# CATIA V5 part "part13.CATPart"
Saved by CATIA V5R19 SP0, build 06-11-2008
Part number: part13
Bounding box of the stored display mesh (mm): x -5.243 to 4.306, y 0 to 10, z -0.01 to 15.28
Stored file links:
  U:\Busbar in SheetMetal\Busbar - Copy.CATPart
  Part3.CATPart
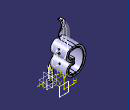
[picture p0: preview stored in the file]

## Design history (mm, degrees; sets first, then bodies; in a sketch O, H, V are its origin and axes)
SheetMetalParameters1: BendRadius 0.7, ReliefAxialLength 2, ReliefRadialLength 1, MinimumBendRadius 0, Thickness 0.8, KFactor 0.31076 {= log(min(100,max(20*SheetMetalParameters1.BendRadius,SheetMetalParameters1.Thickness)/SheetMetalParameters1.Thickness))/log(100)/2}
Set1
  Plane1: type Offset, Offset 1, RefPlane zx-plane
  Plane2: type Offset, Offset 4, RefPlane Plane1
  Plane3: type Offset, Offset 0.01, RefPlane Plane1
  Plane4: type Offset, Offset 0.1, RefPlane Plane2, reversed
  Sketch1 on zx-plane, origin (0, 0, 0), H (-1, 0, 0), V (0, 0, 1)
    arc A1 centre (-1.3046, 11.0693) radius 6 from (2.5521, 6.473) to (3.2916, 14.926) ccw
    arc A2 centre (5, 2) radius 5 from (1.7861, 5.8302) to (0, 2) ccw
    line L1 (0, 2) -> (0, 0)
    point P4 (0, 0)
    line L2 (1.7861, 5.8302) -> (2.5521, 6.473)
    construction line L3 (-1.3046, 11.0693) -> (2.5521, 6.473)
    construction line L4 (-1.3046, 11.0693) -> (3.2916, 14.926)
    point P7 (3.2916, 14.926)
    construction line L5 (5, 2) -> (1.7861, 5.8302)
    axis line L6 (5, 2) -> (0, 2)
    length L1 = 2
    radius A2 = 5
    angle L5 L6 = 50
    length L2 = 1
    radius A1 = 6
    angle L4 L3 = 90
    tangency: L1 A2, L2 A2, A1 L2
    horizontal: L6 H
    coincidence: P4 O
  Sketch2 on Plane3, origin (0, 1.01, 0), H (-1, 0, 0), V (0, 0, 1)
    arc A1 centre (-1.3046, 11.0693) radius 6 from (2.5521, 6.473) to (3.2916, 14.926) ccw
    point P2 (2.5521, 6.473)
    point P3 (3.2916, 14.926)
    reference projected point E1 (3.2916, 14.926) from Sketch1.P7
    reference projected point E2 (2.5521, 6.473) from vertex [element of Sketch1 | element of Sketch1]
    reference projected arc E3 centre (-1.3046, 11.0693) radius 6 from (2.5521, 6.473) to (3.2916, 14.926) ccw from Sketch1.A1
    coincidence: P3 E1, P2 E2, A1 E3
  Sketch3 on Plane2, origin (0, 5, 0), H (-1, 0, 0), V (0, 0, 1)
    construction line L1 (-1.3046, 14.5693) -> (-1.3046, 7.5693)
    construction line L2 (1.1954, 11.0693) -> (-3.8046, 11.0693)
    point P3 (1.1954, 11.0693)
    point P5 (-1.3046, 11.0693)
    ellipse A1 centre (-1.3046, 11.0693) semi-axes 3.5, 2.5 rotation 270 from (-1.3046, 7.5693) to (-1.3046, 14.5693)
    line L3 (-1.3046, 14.5693) -> (-2.3046, 14.5693)
    line L4 (-1.3046, 7.5693) -> (-2.3046, 7.5693)
    construction line L5 (-2.3046, 14.5693) -> (-2.3046, 7.5693)
    arc A2 centre (-2.3046, 13.1193) radius 1.45 from (-2.3046, 14.5693) to (-2.3046, 11.6693) ccw
    point P8 (-2.3046, 13.1193)
    point P9 (-2.3046, 11.6693)
    arc A3 centre (-2.3046, 9.0193) radius 1.45 from (-2.3046, 10.4693) to (-2.3046, 7.5693) ccw
    point P10 (-2.3046, 9.0193)
    point P11 (-2.3046, 10.4693)
    point P12 (-2.3046, 11.6693)
    line L6 (-2.3046, 11.6693) -> (-1.7046, 11.6693)
    line L7 (-2.3046, 10.4693) -> (-1.7046, 10.4693)
    point P14 (-2.3046, 10.4693)
    construction line L8 (-1.7046, 10.4693) -> (-1.7046, 11.6693)
    axis line L9 (-1.7046, 11.0693) -> (-3.8046, 11.0693)
    point P16 (-1.7046, 11.0693)
    construction circle A4 centre (-1.3046, 11.0693) radius 6
    reference projected arc E1 centre (-1.3046, 11.0693) radius 6 from (2.5521, 6.473) to (3.2916, 14.926) ccw from Sketch1.A1
    "Radius" A1 = 3.5
    distance A1 L1 = 2.5
    distance L5 L1 = 1
    distance L8 L5 = 0.6
    radius A2 = 1.45
    distance L6 L7 = 1.2
    vertical: L1 V, L5 V, L8 V
    horizontal: L2 H, L3 H, L4 H, L9 H
    midpoint: P5 L2, P5 L1, P16 L8
    coincidence: A1 P3, P8 L5, A2 P9, P9 L5, P10 L5, L5 P11, L5 P12, P14 A3, A4 E1
    tangency: A2 L3, A3 L4, L6 A2, L7 A3, A1 L4, A1 L3
  Sketch4 on Plane4, origin (0, 4.9, 0), H (-1, 0, 0), V (0, 0, 1)
    axis line L1 (-1.3046, 14.5693) -> (-1.3046, 7.5693)
    point P1 (-1.3046, 14.5693)
    point P2 (-1.3046, 7.5693)
    point P3 (-1.3046, 11.0693)
    ellipse A1 centre (-1.3046, 11.0693) semi-axes 3.5, 2.5 rotation 90 from (-1.3046, 7.5693) to (-1.3046, 14.5693)
    reference projected point E1 (-1.3046, 14.5693) from vertex [element of Sketch3 | element of Sketch3]
    reference projected point E2 (-1.3046, 7.5693) from vertex [element of Sketch3 | element of Sketch3]
    reference projected curve E3 from Sketch3.A1
    vertical: L1 V
    midpoint: P3 L1
    coincidence: P1 E1, P2 E2, A1 E3
  Extrude1: Lim1 3, Lim2 0, FirstUpto Plane1, Element1 Sketch1, Direction zx-plane
  Extrude2: Lim1 3, Lim2 0, FirstUpto Plane1, Element1 Sketch2, Direction Plane3
  Extrude3: Lim1 3, Lim2 0, FirstUpto Plane2, Element1 Sketch4, Direction Plane4
  Extrude4: Lim1 5, Lim2 0, Element1 Sketch3, Direction Plane2
  Loft1: Sections (Sketch2; Sketch4), EndSectionTangent Plane4, StartSectionTangent Plane3
  Sketch5 on xy-plane, origin (0, 0, 0), H (1, 0, 0), V (0, 1, 0)
    point P1 (0, 0)
    line L1 (0, 0) -> (0, 1)
    point P3 (-18.703, -26.5)
    length L1 = 1
    distance P1 H = 0
    vertical: L1 V
    coincidence: L1 O
  Extrude5: Lim1 0.01, Lim2 0, Element1 Sketch5, Direction xy-plane
  Join1: Elements (Extrude5; Extrude1; Extrude2; Loft1; Extrude3; Extrude4)
Body1 (main body)
  Hopper1: Hopper_ReferenceEdge edge of Extrude5, Hopper_Thickness 0.8, HopperFixedSideType 0, Hopper_NeutralFiber 2, Hopper_Surface Join1, Hopper_DeductionTable SheetMetalParameters1, KFacteur 0.31076 {= SheetMetalParameters1.KFactor}, HopperType 0, Hopper_InvariantPoint vertex [face of Extrude5 from Sketch5.L1]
